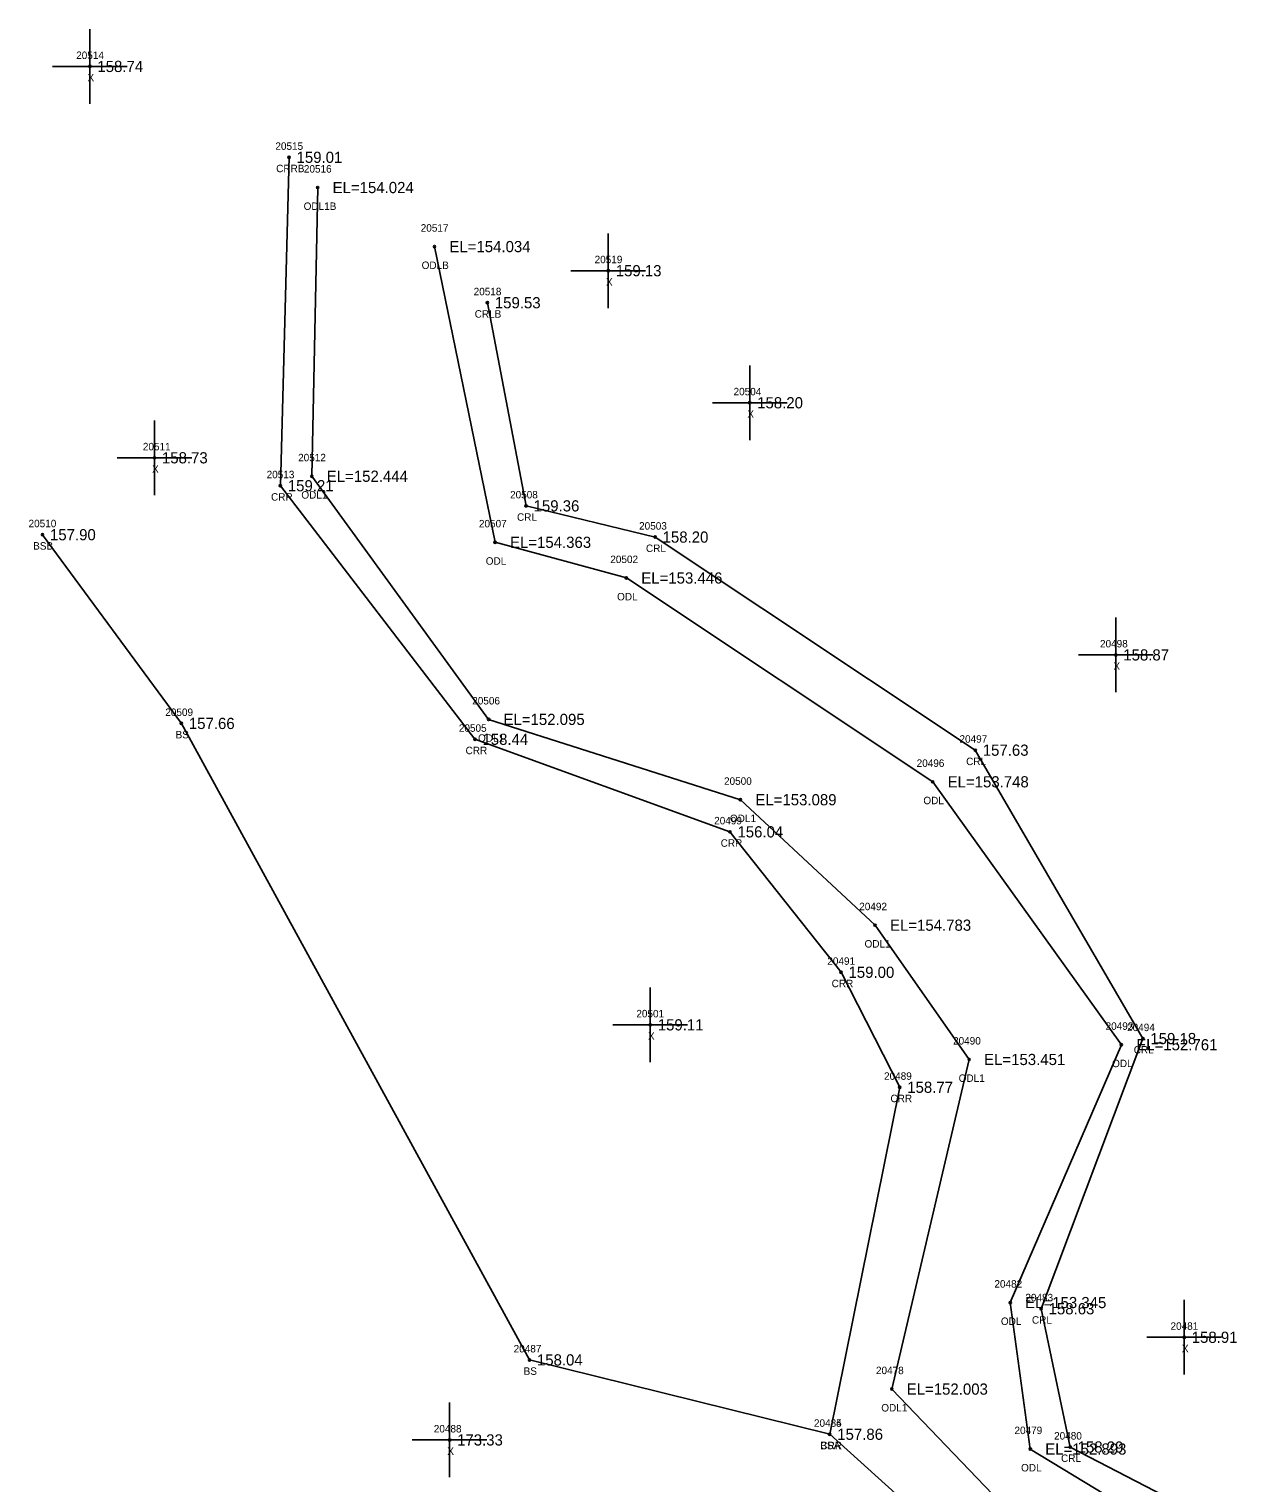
# Model space of a CAD drawing. Extents: x 2279528 to 2280976, y 1061373 to 1062235.
# Drawn here: x 2279942 to 2280104.6, y 1061995.9 to 1062190.6 of the extents above; entities that cross this region are included whole.
import ezdxf

# ---------------------------------------------------------------- set-up
doc = ezdxf.new("R2010")
doc.units = 0
for name, color, linetype in [('RD_DTM_BkLn2', 7, 'Continuous'), ('RD_DTM_BkLn_txCode', 7, 'Continuous'), ('RD_EX_H2O', 7, 'Continuous'), ('RD_EX_H2O_txCode', 7, 'Continuous'), ('RD_EX_Misc', 7, 'Continuous'), ('RD_EX_Misc_txCode', 7, 'Continuous'), ('RD_EX_TX_H2O_ELEV', 7, 'Continuous'), ('RD_EX_TX_Misc_ELEV', 7, 'Continuous'), ('RD_SMD_Locator', 7, 'Continuous')]:
    doc.layers.add(name, color=color, linetype=linetype)

msp = doc.modelspace()

# ---------------------------------------------------------------- linework, layer by layer
at = {"layer": 'RD_DTM_BkLn2'}
msp.add_lwpolyline([(2280049.27, 1062002.4), (2280009.03, 1062012.36), (2279962.39, 1062097.61), (2279943.78, 1062122.89)], dxfattribs=at)
at = {"layer": 'RD_EX_H2O'}
for points in [[(2280211.16, 1061800.79), (2280200.18, 1061802.95), (2280195.55, 1061801.16), (2280185.62, 1061809.36), (2280166.4, 1061839.27), (2280165.19, 1061847.77), (2280176.13, 1061895.97), (2280173.38, 1061913.11), (2280146.96, 1061940.88), (2280090.97, 1061964.76), (2280049.27, 1062002.4), (2280058.65, 1062048.88), (2280050.78, 1062064.28), (2280035.9, 1062083.09), (2280001.73, 1062095.49), (2279975.65, 1062129.45), (2279976.82, 1062173.44)], [(2280168.33, 1061843.42), (2280183.83, 1061895.62), (2280179.4, 1061916.69), (2280147.37, 1061943.73), (2280094.98, 1061969.47), (2280057.58, 1062008.45), (2280067.95, 1062052.6), (2280055.34, 1062070.59), (2280037.3, 1062087.39), (2280003.55, 1062098.15), (2279979.87, 1062130.72), (2279980.65, 1062169.39)], [(2280245.52, 1061819.46), (2280233.94, 1061826.17), (2280221.09, 1061822.97), (2280184.1, 1061845.49), (2280188.88, 1061876.01), (2280197.41, 1061894.2), (2280195.18, 1061912.5), (2280158.13, 1061956.7), (2280101.97, 1061984.74), (2280076.14, 1062000.42), (2280073.45, 1062020.04), (2280088.34, 1062054.57), (2280063.06, 1062089.79), (2280022.01, 1062117.09), (2280004.42, 1062121.87), (2279996.3, 1062161.48)], [(2280247.67, 1061820.22), (2280254.15, 1061833.04), (2280250.13, 1061833.61), (2280244.17, 1061836.72), (2280240.97, 1061826.97), (2280234.88, 1061827.59), (2280194.99, 1061843.09), (2280190.85, 1061845.93), (2280191.54, 1061875.47), (2280203.31, 1061891.05), (2280202.74, 1061912.57), (2280161.92, 1061962.77), (2280106.66, 1061987.64), (2280081.48, 1062000.69), (2280077.59, 1062019.21), (2280091.23, 1062055.4), (2280068.77, 1062094.03), (2280025.87, 1062122.57), (2280008.58, 1062126.75), (2280003.39, 1062153.96)]]:
    msp.add_lwpolyline(points, dxfattribs=at)
at = {"layer": 'RD_EX_Misc'}
for p, q in [((2279950.13, 1062180.61), (2279950.13, 1062190.61)), ((2279945.13, 1062185.61), (2279955.13, 1062185.61)), ((2280019.59, 1062153.25), (2280019.59, 1062163.25)), ((2280014.59, 1062158.25), (2280024.59, 1062158.25)), ((2280038.54, 1062135.56), (2280038.54, 1062145.56)), ((2280033.54, 1062140.56), (2280043.54, 1062140.56)), ((2279958.78, 1062128.19), (2279958.78, 1062138.19)), ((2279953.78, 1062133.19), (2279963.78, 1062133.19)), ((2280087.6, 1062101.79), (2280087.6, 1062111.79)), ((2280082.6, 1062106.79), (2280092.6, 1062106.79)), ((2280025.22, 1062052.24), (2280025.22, 1062062.24)), ((2280020.22, 1062057.24), (2280030.22, 1062057.24)), ((2280096.77, 1062010.39), (2280096.77, 1062020.39)), ((2280091.77, 1062015.39), (2280101.77, 1062015.39)), ((2279998.33, 1061996.64), (2279998.33, 1062006.64)), ((2279993.33, 1062001.64), (2280003.33, 1062001.64))]:
    msp.add_line(p, q, dxfattribs=at)
at = {"layer": 'RD_SMD_Locator'}
for centre in [(2279950.13, 1062185.61), (2279976.82, 1062173.44), (2279980.65, 1062169.39), (2279996.3, 1062161.48), (2280019.59, 1062158.25), (2280003.39, 1062153.96), (2280038.54, 1062140.56), (2279958.78, 1062133.19), (2279979.87, 1062130.72), (2279975.65, 1062129.45), (2280008.58, 1062126.75), (2279943.78, 1062122.89), (2280025.87, 1062122.57), (2280004.42, 1062121.87), (2280022.01, 1062117.09), (2280087.6, 1062106.79), (2279962.39, 1062097.61), (2280003.55, 1062098.15), (2280001.73, 1062095.49), (2280068.77, 1062094.03), (2280063.06, 1062089.79), (2280037.3, 1062087.39), (2280035.9, 1062083.09), (2280055.34, 1062070.59), (2280050.78, 1062064.28), (2280025.22, 1062057.24), (2280088.34, 1062054.57), (2280091.23, 1062055.4), (2280067.95, 1062052.6), (2280058.65, 1062048.88), (2280073.45, 1062020.04), (2280077.59, 1062019.21), (2280096.77, 1062015.39), (2280009.03, 1062012.36), (2280057.58, 1062008.45), (2279998.33, 1062001.64), (2280049.27, 1062002.4), (2280049.27, 1062002.4), (2280076.14, 1062000.42), (2280081.48, 1062000.69)]:
    msp.add_circle(centre, 0.15, dxfattribs=at)

# ---------------------------------------------------------------- texts
at = {"layer": 'RD_DTM_BkLn_txCode'}
for s, p in [('20510', (2279941.91, 1062123.89)), ('BSB', (2279942.53, 1062120.89)), ('20509', (2279960.23, 1062098.61)), ('BS', (2279961.61, 1062095.61)), ('20487', (2280006.91, 1062013.36)), ('BS', (2280008.25, 1062010.36)), ('20485', (2280047.15, 1062003.4)), ('BSA', (2280048, 1062000.4))]:
    msp.add_text(s, height=1, dxfattribs=at).set_placement(p)
at = {"layer": 'RD_EX_H2O_txCode'}
for s, p in [('20515', (2279974.98, 1062174.44)), ('CRRB', (2279975.09, 1062171.44)), ('20516', (2279978.8, 1062171.39)), ('ODL1B', (2279978.77, 1062166.39)), ('20517', (2279994.46, 1062163.48)), ('ODLB', (2279994.58, 1062158.48)), ('20518', (2280001.55, 1062154.96)), ('CRLB', (2280001.69, 1062151.96)), ('20512', (2279978.03, 1062132.72)), ('20513', (2279973.81, 1062130.45)), ('CRR', (2279974.4, 1062127.45)), ('ODL1', (2279978.46, 1062127.72)), ('20508', (2280006.43, 1062127.75)), ('20507', (2280002.26, 1062123.87)), ('CRL', (2280007.36, 1062124.75)), ('20503', (2280023.72, 1062123.57)), ('20502', (2280019.86, 1062119.09)), ('CRL', (2280024.64, 1062120.57)), ('ODL', (2280003.17, 1062118.87)), ('ODL', (2280020.77, 1062114.09)), ('20506', (2280001.36, 1062100.15)), ('20505', (2279999.57, 1062096.49)), ('ODL1', (2280002.14, 1062095.15)), ('20497', (2280066.65, 1062095.03)), ('CRR', (2280000.47, 1062093.49)), ('CRL', (2280067.54, 1062092.03)), ('20496', (2280060.91, 1062091.79)), ('20500', (2280035.1, 1062089.39)), ('ODL', (2280061.81, 1062086.79)), ('20499', (2280033.78, 1062084.09)), ('ODL1', (2280035.89, 1062084.39)), ('CRR', (2280034.65, 1062081.09)), ('20492', (2280053.22, 1062072.59)), ('ODL1', (2280053.93, 1062067.59)), ('20491', (2280048.94, 1062065.28)), ('CRR', (2280049.52, 1062062.28)), ('20493', (2280086.23, 1062056.57)), ('20494', (2280089.11, 1062056.4)), ('20490', (2280065.79, 1062054.6)), ('CRL', (2280090, 1062053.4)), ('ODL', (2280087.1, 1062051.57)), ('20489', (2280056.54, 1062049.88)), ('ODL1', (2280066.54, 1062049.6)), ('CRR', (2280057.4, 1062046.88)), ('20482', (2280071.33, 1062022.04)), ('20483', (2280075.48, 1062020.21)), ('ODL', (2280072.2, 1062017.04)), ('CRL', (2280076.36, 1062017.21)), ('20478', (2280055.46, 1062010.45)), ('ODL1', (2280056.17, 1062005.45)), ('20484', (2280047.15, 1062003.4)), ('20479', (2280074.02, 1062002.42)), ('CRR', (2280048.01, 1062000.4)), ('20480', (2280079.33, 1062001.69)), ('CRL', (2280080.26, 1061998.69)), ('ODL', (2280074.9, 1061997.42))]:
    msp.add_text(s, height=1, dxfattribs=at).set_placement(p)
at = {"layer": 'RD_EX_Misc_txCode'}
for s, p in [('20514', (2279948.29, 1062186.61)), ('X', (2279949.81, 1062183.61)), ('20519', (2280017.76, 1062159.25)), ('X', (2280019.28, 1062156.25)), ('20504', (2280036.38, 1062141.56)), ('X', (2280038.23, 1062138.56)), ('20511', (2279957.23, 1062134.19)), ('X', (2279958.46, 1062131.19)), ('20498', (2280085.48, 1062107.79)), ('X', (2280087.28, 1062104.79)), ('20501', (2280023.35, 1062058.24)), ('X', (2280024.91, 1062055.24)), ('20481', (2280094.93, 1062016.39)), ('X', (2280096.45, 1062013.39)), ('20488', (2279996.21, 1062002.64)), ('X', (2279998.02, 1061999.64))]:
    msp.add_text(s, height=1, dxfattribs=at).set_placement(p)
at = {"layer": 'RD_EX_TX_H2O_ELEV'}
for s, p in [('159.01', (2279977.82, 1062172.69)), ('EL=154.024', (2279982.65, 1062168.64)), ('EL=154.034', (2279998.3, 1062160.73)), ('159.53', (2280004.39, 1062153.21)), ('159.21', (2279976.65, 1062128.7)), ('EL=152.444', (2279981.87, 1062129.97)), ('159.36', (2280009.58, 1062126)), ('EL=154.363', (2280006.42, 1062121.12)), ('158.20', (2280026.87, 1062121.82)), ('EL=153.446', (2280024.01, 1062116.34)), ('EL=152.095', (2280005.55, 1062097.4)), ('158.44', (2280002.73, 1062094.74)), ('157.63', (2280069.77, 1062093.28)), ('EL=153.748', (2280065.06, 1062089.04)), ('EL=153.089', (2280039.3, 1062086.64)), ('156.04', (2280036.9, 1062082.34)), ('EL=154.783', (2280057.34, 1062069.84)), ('159.00', (2280051.78, 1062063.53)), ('159.18', (2280092.23, 1062054.65)), ('EL=152.761', (2280090.34, 1062053.82)), ('EL=153.451', (2280069.95, 1062051.85)), ('158.77', (2280059.65, 1062048.13)), ('EL=153.345', (2280075.45, 1062019.29)), ('158.63', (2280078.59, 1062018.46)), ('EL=152.003', (2280059.58, 1062007.7)), ('157.86', (2280050.27, 1062001.65)), ('158.29', (2280082.48, 1061999.94)), ('EL=152.893', (2280078.14, 1061999.67))]:
    msp.add_text(s, height=1.5, dxfattribs=at).set_placement(p)
at = {"layer": 'RD_EX_TX_Misc_ELEV'}
for s, p in [('158.74', (2279951.13, 1062184.86)), ('159.13', (2280020.59, 1062157.5)), ('158.20', (2280039.54, 1062139.81)), ('158.73', (2279959.78, 1062132.44)), ('157.90', (2279944.78, 1062122.14)), ('158.87', (2280088.6, 1062106.04)), ('157.66', (2279963.39, 1062096.86)), ('159.11', (2280026.22, 1062056.49)), ('158.91', (2280097.77, 1062014.64)), ('158.04', (2280010.03, 1062011.61)), ('173.33', (2279999.33, 1062000.89)), ('157.86', (2280050.27, 1062001.65))]:
    msp.add_text(s, height=1.5, dxfattribs=at).set_placement(p)

doc.saveas('drawing.dxf')
